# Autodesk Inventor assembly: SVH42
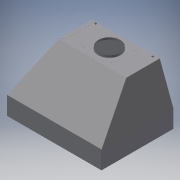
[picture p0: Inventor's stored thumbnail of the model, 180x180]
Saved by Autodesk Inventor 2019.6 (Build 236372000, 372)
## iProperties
Company: none
Created: 2025-04
Part Number: SVH42
Description: CATIA V5 STEP
Document SubType Name: Assembly
Designer: MMAK
Authority: none
Title: C:\Users\MMAK\Documents\SmarTeam\WEBSITE CAD\2025 TRADEWIND HOODS\SVH42.stp
Author: none
Revision Number: ANY
Sending System: CATIA V5 STEP AP203 v2
Preprocessor: CATIA Unofficial Packaging Version SP2
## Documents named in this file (10)
- C:\Users\MMAK\Documents\SmarTeam\WEBSITE CAD\2025 TRADEWIND HOODS\SVH42.iam
- C:\Users\MMAK\Documents\SmarTeam\WEBSITE CAD\2025 TRADEWIND HOODS\P7242-xx-07 face.ipt
- C:\Users\MMAK\Documents\SmarTeam\WEBSITE CAD\2025 TRADEWIND HOODS\x7242-xx-05 SS Rear Angle.ipt
- C:\Users\MMAK\Documents\SmarTeam\WEBSITE CAD\2025 TRADEWIND HOODS\Blower Mount Plate and Collar.iam
- C:\Users\MMAK\Documents\SmarTeam\WEBSITE CAD\2025 TRADEWIND HOODS\P72xx-xx-03 left end.ipt
- C:\Users\MMAK\Documents\SmarTeam\WEBSITE CAD\2025 TRADEWIND HOODS\x7242-xx-11 divider.ipt
- C:\Users\MMAK\Documents\SmarTeam\WEBSITE CAD\2025 TRADEWIND HOODS\P72xx-xx-02 right end.ipt
- C:\Users\MMAK\Documents\SmarTeam\WEBSITE CAD\2025 TRADEWIND HOODS\P7242-12-01 back.ipt
- C:\Users\MMAK\Documents\SmarTeam\WEBSITE CAD\2025 TRADEWIND HOODS\Blowers Mount Plate Rear.ipt
- C:\Users\MMAK\Documents\SmarTeam\WEBSITE CAD\2025 TRADEWIND HOODS\x7242-xx-32 lightbar.ipt
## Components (9 placed, 9 different names)
1. NAUO1
2. NAUO7
3. NAUO6 [sub-assembly]
4. NAUO4
5. NAUO9
6. NAUO3
7. NAUO2
8. NAUO5
9. NAUO12
